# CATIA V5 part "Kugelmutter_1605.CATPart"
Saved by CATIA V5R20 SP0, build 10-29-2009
Part number: Kugelmutter_1605
Bounding box of the stored display mesh (mm): x 0 to 43.5, y -23.998 to 23.998, z -20 to 20
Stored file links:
  C:\Users\Andi\Desktop\Plasma\Kugelmutter_1605.CATPart
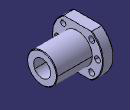
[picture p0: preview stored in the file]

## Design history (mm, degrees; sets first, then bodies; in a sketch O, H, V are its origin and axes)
Body1 (main body)
  Sketch1 on yz-plane, origin (0, 0, 0), H (0, 1, 0), V (0, 0, 1)
    arc A1 centre (0, 0) radius 24 from (13.2665, -20) to (13.2665, 20) ccw
    line L1 (-13.2665, 20) -> (13.2665, 20)
    point P1 (-13.2665, 20)
    line L2 (-13.2665, -20) -> (13.2665, -20)
    arc A2 centre (0, 0) radius 24 from (-13.2665, 20) to (-13.2665, -20) ccw
    radius A1 = 24
    distance L1 H = 20
    distance L1 L2 = 40
    coincidence: P1 A1, A1 A2
    horizontal: L1 H, L2 H
  Pad1: profile Sketch1, direction (1, 0, 0), length 10
  Sketch2 on face of Pad1, origin (10, 0, 0), H (0, 1, 0), V (0, 0, 1)
    circle A1 centre (0, 0) radius 14
    radius A1 = 14
  Pad2: profile Sketch2, direction (1, 0, 0), length 33.5
  Sketch3 on face of Pad1, origin (0, -10.3471, -2.9387), H (0, 1, 0), V (0, 0, -1)
    point P1 (-8.6529, -2.9387)
    construction circle A1 centre (10.3471, -2.9387) radius 19
    reference projected arc E1 centre (10.3471, -2.9387) radius 24 from (23.6136, -22.9387) to (23.6136, 17.0613) ccw from edge [face of Pad1 | face of Pad1]
    reference intersected line E2 through (0, -2.9387) direction (1, 0) from xy-plane
    radius A1 = 19
    concentricity: A1 E1
    coincidence: P1 A1, E2 P1
  Hole1: placed by Sketch3, at (0, -19, 0) direction (1, 0, 0), diameter 4.8, through (limit type 3)
  Sketch4 on face of Pad1, origin (0, 16.6717, 0.0298), H (0, 1, 0), V (0, 0, -1)
    point P1 (2.3283, 0.0298)
    construction circle A1 centre (-16.6717, 0.0298) radius 19
    reference projected arc E1 centre (-16.6717, 0.0298) radius 24 from (-3.4052, -19.9702) to (-3.4052, 20.0298) ccw from edge [face of Pad1 | face of Pad1]
    reference intersected line E2 through (0, 0.0298) direction (1, 0) from xy-plane
    radius A1 = 19
    concentricity: A1 E1
    coincidence: P1 A1, P1 E2
  Hole2: placed by Sketch4, at (0, 19, 0) direction (1, 0, 0), diameter 5.5, through (limit type 3)
  CircPattern1: of Hole1, Hole2, instances 3, angular step 45, axis from face of Pad1, AngularPosition 2
  Sketch5 on face of Pad1, origin (0, -8.1526, 3.2195), H (0, 1, 0), V (0, 0, -1)
    point P1 (8.1526, 3.2195)
    reference projected arc E1 centre (8.1526, 3.2195) radius 24 from (21.4191, -16.7805) to (21.4191, 23.2195) ccw from edge [face of Pad1 | face of Pad1]
    concentricity: P1 E1
  Hole3: placed by Sketch5, at (0, 0, 0) direction (1, 0, 0), diameter 16, through (limit type 3)
  Chamfer1: length 0.5, angle 45, on edge [face of Pad2 | face of Pad2]; edge [face of Pad1 | face of Pad1] (x4)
